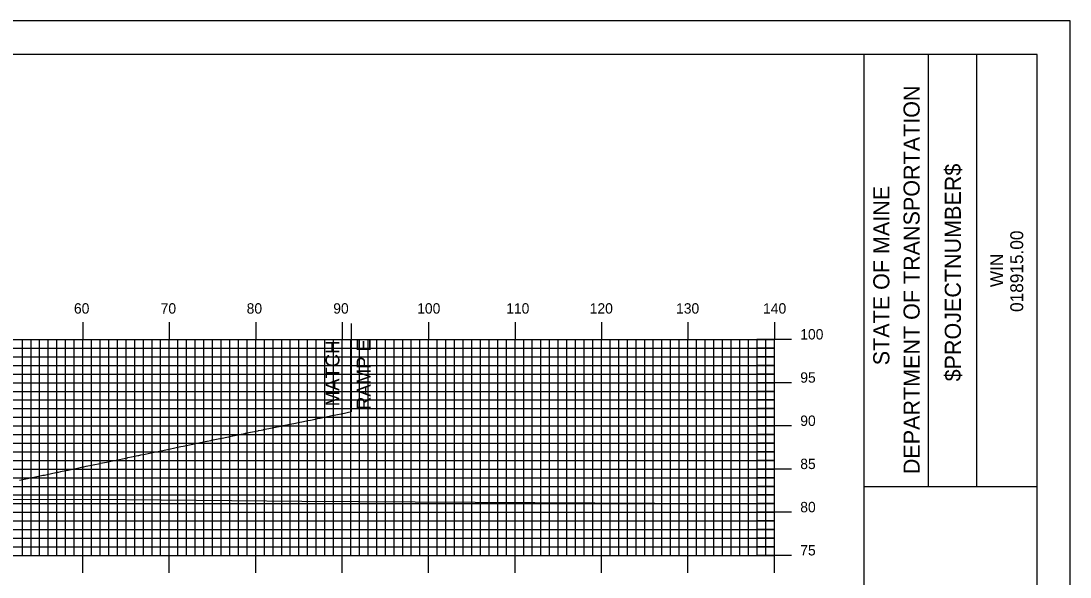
# Model space of a CAD drawing. Extents: x 1757069 to 1757412, y 442591 to 442811.
# Drawn here: x 1757287.4 to 1757408.8, y 442746.2 to 442810.5 of the extents above; entities that cross this region are included whole.
import ezdxf

# ---------------------------------------------------------------- set-up
doc = ezdxf.new("R2010")
doc.units = 0
for name, color, linetype in [('ANNOTATION', 7, 'Continuous'), ('BORDER', 7, 'Continuous'), ('D_Roadway_Centerline', 7, 'Continuous'), ('D_Roadway_SubGrade', 7, 'Continuous'), ('H_V ANNOTATION', 7, 'Continuous'), ('MAJOR', 7, 'Continuous'), ('MINOR', 7, 'Continuous'), ('PLOT BOUNDARY', 7, 'Continuous'), ('S_Roadway_Centerline', 7, 'Continuous')]:
    doc.layers.add(name, color=color, linetype=linetype)

msp = doc.modelspace()

# ---------------------------------------------------------------- linework, layer by layer
at = {"layer": 'BORDER'}
for p, q in [((1757385, 442596.67), (1757385, 442806.67)), ((1757392.45, 442756.66), (1757392.45, 442806.66)), ((1757398.04, 442756.66), (1757398.04, 442806.66)), ((1757385, 442756.65), (1757405, 442756.65))]:
    msp.add_line(p, q, dxfattribs=at)
msp.add_lwpolyline([(1757085, 442596.67), (1757405, 442596.67), (1757405, 442806.67), (1757085, 442806.67)], close=True, dxfattribs=at)
at = {"layer": 'D_Roadway_Centerline'}
msp.add_lwpolyline([(1757287.28, 442757.38), (1757289.48, 442757.84), (1757289.97, 442757.95), (1757290.08, 442757.97), (1757290.15, 442757.98), (1757291.11, 442758.18), (1757291.68, 442758.31), (1757291.74, 442758.32), (1757291.78, 442758.32), (1757292.04, 442758.38), (1757292.21, 442758.42), (1757292.89, 442758.56), (1757293.39, 442758.66), (1757293.96, 442758.78), (1757294.44, 442758.88), (1757294.73, 442758.94), (1757295, 442759), (1757295.79, 442759.16), (1757296.59, 442759.33), (1757296.61, 442759.33), (1757296.64, 442759.34), (1757297.33, 442759.48), (1757298.17, 442759.66), (1757298.44, 442759.72), (1757298.82, 442759.79), (1757299.19, 442759.87), (1757299.74, 442759.99), (1757299.77, 442759.99), (1757299.81, 442760), (1757300.24, 442760.09), (1757300.97, 442760.24), (1757301.09, 442760.26), (1757301.3, 442760.31), (1757301.81, 442760.41), (1757302.85, 442760.63), (1757302.93, 442760.65), (1757303.11, 442760.68), (1757303.46, 442760.76), (1757304.39, 442760.95), (1757304.59, 442760.99), (1757305.23, 442761.12), (1757305.38, 442761.15), (1757305.92, 442761.27), (1757306.19, 442761.32), (1757307.32, 442761.56), (1757307.34, 442761.56), (1757307.44, 442761.58), (1757307.47, 442761.59), (1757307.65, 442761.62), (1757307.84, 442761.66), (1757308.94, 442761.89), (1757308.99, 442761.9), (1757309.4, 442761.98), (1757309.5, 442762.01), (1757310.44, 442762.2), (1757310.51, 442762.21), (1757311.46, 442762.41), (1757311.47, 442762.41), (1757311.93, 442762.51), (1757311.96, 442762.51), (1757312.72, 442762.67), (1757313.33, 442762.8), (1757313.4, 442762.81), (1757313.41, 442762.81), (1757313.49, 442762.83), (1757313.58, 442762.85), (1757314.87, 442763.11), (1757314.93, 442763.12), (1757315.22, 442763.18), (1757315.45, 442763.23), (1757315.51, 442763.24), (1757315.7, 442763.28), (1757316.32, 442763.41), (1757316.68, 442763.48), (1757317.51, 442763.65), (1757317.67, 442763.69), (1757317.77, 442763.71), (1757318.57, 442763.87), (1757319.21, 442764), (1757319.35, 442764.03), (1757319.49, 442764.06), (1757320.14, 442764.19), (1757320.64, 442764.29), (1757320.94, 442764.35), (1757321.46, 442764.46), (1757321.88, 442764.55), (1757322.05, 442764.58), (1757322.19, 442764.61), (1757322.54, 442764.68), (1757323.24, 442764.82), (1757323.4, 442764.86), (1757323.41, 442764.86), (1757323.46, 442764.87), (1757323.68, 442764.91), (1757324.86, 442765.15), (1757325.32, 442765.25), (1757325.33, 442765.25), (1757325.35, 442765.25), (1757325.65, 442765.31)], dxfattribs=at)
at = {"layer": 'D_Roadway_SubGrade'}
msp.add_line((1757325.65, 442775.53), (1757325.65, 442765.31), dxfattribs=at)
at = {"layer": 'MAJOR'}
for p, q in [((1757294.6, 442775.67), (1757294.6, 442773.67)), ((1757304.6, 442775.67), (1757304.6, 442773.67)), ((1757314.6, 442775.67), (1757314.6, 442773.67)), ((1757324.6, 442775.67), (1757324.6, 442773.67)), ((1757334.6, 442775.67), (1757334.6, 442773.67)), ((1757344.6, 442775.67), (1757344.6, 442773.67)), ((1757354.6, 442775.67), (1757354.6, 442773.67)), ((1757364.6, 442775.67), (1757364.6, 442773.67)), ((1757374.6, 442775.67), (1757374.6, 442773.67)), ((1757094.6, 442773.67), (1757374.6, 442773.67)), ((1757094.6, 442773.67), (1757374.6, 442773.67)), ((1757294.6, 442748.67), (1757294.6, 442773.67)), ((1757304.6, 442748.67), (1757304.6, 442773.67)), ((1757314.6, 442748.67), (1757314.6, 442773.67)), ((1757324.6, 442748.67), (1757324.6, 442773.67)), ((1757334.6, 442748.67), (1757334.6, 442773.67)), ((1757344.6, 442748.67), (1757344.6, 442773.67)), ((1757354.6, 442748.67), (1757354.6, 442773.67)), ((1757364.6, 442748.67), (1757364.6, 442773.67)), ((1757376.6, 442773.67), (1757372.59, 442773.67)), ((1757374.6, 442748.67), (1757374.6, 442773.67)), ((1757374.6, 442748.67), (1757374.6, 442773.67)), ((1757094.6, 442768.67), (1757374.6, 442768.67)), ((1757376.6, 442768.67), (1757372.59, 442768.67)), ((1757094.6, 442763.67), (1757374.6, 442763.67)), ((1757376.6, 442763.67), (1757372.59, 442763.67)), ((1757094.6, 442758.67), (1757374.6, 442758.67)), ((1757376.6, 442758.67), (1757372.59, 442758.67)), ((1757094.6, 442753.67), (1757374.6, 442753.67)), ((1757376.6, 442753.67), (1757372.59, 442753.67)), ((1757094.6, 442748.67), (1757374.6, 442748.67)), ((1757094.6, 442748.67), (1757374.6, 442748.67)), ((1757294.6, 442746.66), (1757294.6, 442748.67)), ((1757304.6, 442746.66), (1757304.6, 442748.67)), ((1757314.6, 442746.66), (1757314.6, 442748.67)), ((1757324.6, 442746.66), (1757324.6, 442748.67)), ((1757334.6, 442746.66), (1757334.6, 442748.67)), ((1757344.6, 442746.66), (1757344.6, 442748.67)), ((1757354.6, 442746.66), (1757354.6, 442748.67)), ((1757364.6, 442746.66), (1757364.6, 442748.67)), ((1757376.6, 442748.67), (1757372.59, 442748.67)), ((1757374.6, 442746.66), (1757374.6, 442748.67))]:
    msp.add_line(p, q, dxfattribs=at)
at = {"layer": 'MINOR'}
for p, q in [((1757287.6, 442748.67), (1757287.6, 442773.67)), ((1757288.6, 442748.67), (1757288.6, 442773.67)), ((1757289.6, 442748.67), (1757289.6, 442773.67)), ((1757290.6, 442748.67), (1757290.6, 442773.67)), ((1757291.6, 442748.67), (1757291.6, 442773.67)), ((1757292.6, 442748.67), (1757292.6, 442773.67)), ((1757293.6, 442748.67), (1757293.6, 442773.67)), ((1757295.6, 442748.67), (1757295.6, 442773.67)), ((1757296.6, 442748.67), (1757296.6, 442773.67)), ((1757297.6, 442748.67), (1757297.6, 442773.67)), ((1757298.6, 442748.67), (1757298.6, 442773.67)), ((1757299.6, 442748.67), (1757299.6, 442773.67)), ((1757300.6, 442748.67), (1757300.6, 442773.67)), ((1757301.6, 442748.67), (1757301.6, 442773.67)), ((1757302.6, 442748.67), (1757302.6, 442773.67)), ((1757303.6, 442748.67), (1757303.6, 442773.67)), ((1757305.6, 442748.67), (1757305.6, 442773.67)), ((1757306.6, 442748.67), (1757306.6, 442773.67)), ((1757307.6, 442748.67), (1757307.6, 442773.67)), ((1757308.6, 442748.67), (1757308.6, 442773.67)), ((1757309.6, 442748.67), (1757309.6, 442773.67)), ((1757310.6, 442748.67), (1757310.6, 442773.67)), ((1757311.6, 442748.67), (1757311.6, 442773.67)), ((1757312.6, 442748.67), (1757312.6, 442773.67)), ((1757313.6, 442748.67), (1757313.6, 442773.67)), ((1757315.6, 442748.67), (1757315.6, 442773.67)), ((1757316.6, 442748.67), (1757316.6, 442773.67)), ((1757317.6, 442748.67), (1757317.6, 442773.67)), ((1757318.6, 442748.67), (1757318.6, 442773.67)), ((1757319.6, 442748.67), (1757319.6, 442773.67)), ((1757320.6, 442748.67), (1757320.6, 442773.67)), ((1757321.6, 442748.67), (1757321.6, 442773.67)), ((1757322.6, 442748.67), (1757322.6, 442773.67)), ((1757323.6, 442748.67), (1757323.6, 442773.67)), ((1757325.6, 442748.67), (1757325.6, 442773.67)), ((1757326.6, 442748.67), (1757326.6, 442773.67)), ((1757327.6, 442748.67), (1757327.6, 442773.67)), ((1757328.6, 442748.67), (1757328.6, 442773.67)), ((1757329.6, 442748.67), (1757329.6, 442773.67)), ((1757330.6, 442748.67), (1757330.6, 442773.67)), ((1757331.6, 442748.67), (1757331.6, 442773.67)), ((1757332.6, 442748.67), (1757332.6, 442773.67)), ((1757333.6, 442748.67), (1757333.6, 442773.67)), ((1757335.6, 442748.67), (1757335.6, 442773.67)), ((1757336.6, 442748.67), (1757336.6, 442773.67)), ((1757337.6, 442748.67), (1757337.6, 442773.67)), ((1757338.6, 442748.67), (1757338.6, 442773.67)), ((1757339.6, 442748.67), (1757339.6, 442773.67)), ((1757340.6, 442748.67), (1757340.6, 442773.67)), ((1757341.6, 442748.67), (1757341.6, 442773.67)), ((1757342.6, 442748.67), (1757342.6, 442773.67)), ((1757343.6, 442748.67), (1757343.6, 442773.67)), ((1757345.6, 442748.67), (1757345.6, 442773.67)), ((1757346.6, 442748.67), (1757346.6, 442773.67)), ((1757347.6, 442748.67), (1757347.6, 442773.67)), ((1757348.6, 442748.67), (1757348.6, 442773.67)), ((1757349.6, 442748.67), (1757349.6, 442773.67)), ((1757350.6, 442748.67), (1757350.6, 442773.67)), ((1757351.6, 442748.67), (1757351.6, 442773.67)), ((1757352.6, 442748.67), (1757352.6, 442773.67)), ((1757353.6, 442748.67), (1757353.6, 442773.67)), ((1757355.6, 442748.67), (1757355.6, 442773.67)), ((1757356.6, 442748.67), (1757356.6, 442773.67)), ((1757357.6, 442748.67), (1757357.6, 442773.67)), ((1757358.6, 442748.67), (1757358.6, 442773.67)), ((1757359.6, 442748.67), (1757359.6, 442773.67)), ((1757360.6, 442748.67), (1757360.6, 442773.67)), ((1757361.6, 442748.67), (1757361.6, 442773.67)), ((1757362.6, 442748.67), (1757362.6, 442773.67)), ((1757363.6, 442748.67), (1757363.6, 442773.67)), ((1757365.6, 442748.67), (1757365.6, 442773.67)), ((1757366.6, 442748.67), (1757366.6, 442773.67)), ((1757367.6, 442748.67), (1757367.6, 442773.67)), ((1757368.6, 442748.67), (1757368.6, 442773.67)), ((1757369.6, 442748.67), (1757369.6, 442773.67)), ((1757370.6, 442748.67), (1757370.6, 442773.67)), ((1757371.6, 442748.67), (1757371.6, 442773.67)), ((1757372.6, 442748.67), (1757372.6, 442773.67)), ((1757373.6, 442748.67), (1757373.6, 442773.67)), ((1757094.6, 442772.67), (1757374.6, 442772.67)), ((1757094.6, 442771.67), (1757374.6, 442771.67)), ((1757374.6, 442772.67), (1757372.59, 442772.67)), ((1757374.6, 442771.67), (1757372.59, 442771.67)), ((1757094.6, 442770.67), (1757374.6, 442770.67)), ((1757374.6, 442770.67), (1757372.59, 442770.67)), ((1757094.6, 442769.67), (1757374.6, 442769.67)), ((1757374.6, 442769.67), (1757372.59, 442769.67)), ((1757094.6, 442767.67), (1757374.6, 442767.67)), ((1757094.6, 442766.67), (1757374.6, 442766.67)), ((1757374.6, 442767.67), (1757372.59, 442767.67)), ((1757374.6, 442766.67), (1757372.59, 442766.67)), ((1757094.6, 442765.67), (1757374.6, 442765.67)), ((1757374.6, 442765.67), (1757372.59, 442765.67)), ((1757094.6, 442764.67), (1757374.6, 442764.67)), ((1757374.6, 442764.67), (1757372.59, 442764.67)), ((1757094.6, 442762.67), (1757374.6, 442762.67)), ((1757374.6, 442762.67), (1757372.59, 442762.67)), ((1757094.6, 442761.67), (1757374.6, 442761.67)), ((1757094.6, 442760.67), (1757374.6, 442760.67)), ((1757374.6, 442761.67), (1757372.59, 442761.67)), ((1757374.6, 442760.67), (1757372.59, 442760.67)), ((1757094.6, 442759.67), (1757374.6, 442759.67)), ((1757374.6, 442759.67), (1757372.59, 442759.67)), ((1757094.6, 442757.67), (1757374.6, 442757.67)), ((1757374.6, 442757.67), (1757372.59, 442757.67)), ((1757094.6, 442756.67), (1757374.6, 442756.67)), ((1757374.6, 442756.67), (1757372.59, 442756.67)), ((1757094.6, 442755.67), (1757374.6, 442755.67)), ((1757094.6, 442754.67), (1757374.6, 442754.67)), ((1757374.6, 442755.67), (1757372.59, 442755.67)), ((1757374.6, 442754.67), (1757372.59, 442754.67)), ((1757094.6, 442752.67), (1757374.6, 442752.67)), ((1757374.6, 442752.67), (1757372.59, 442752.67)), ((1757094.6, 442751.67), (1757374.6, 442751.67)), ((1757374.6, 442751.67), (1757372.59, 442751.67)), ((1757094.6, 442750.67), (1757374.6, 442750.67)), ((1757094.6, 442749.67), (1757374.6, 442749.67)), ((1757374.6, 442750.67), (1757372.59, 442750.67)), ((1757374.6, 442749.67), (1757372.59, 442749.67))]:
    msp.add_line(p, q, dxfattribs=at)
at = {"layer": 'PLOT BOUNDARY'}
msp.add_lwpolyline([(1757068.81, 442590.55), (1757408.81, 442590.55), (1757408.81, 442810.55), (1757068.81, 442810.55)], close=True, dxfattribs=at)
at = {"layer": 'S_Roadway_Centerline'}
msp.add_lwpolyline([(1757094.6, 442753.7), (1757106.02, 442753.69), (1757125.8, 442753.96), (1757135.34, 442753.91), (1757159.12, 442753.84), (1757182.03, 442754.12), (1757202.03, 442754.31), (1757204.09, 442754.32), (1757230.57, 442754.75), (1757249.03, 442754.84), (1757258.63, 442754.86), (1757284.4, 442755.15), (1757295.54, 442755.17), (1757319.95, 442754.95), (1757333.06, 442754.89), (1757374.6, 442754.64)], dxfattribs=at)

# ---------------------------------------------------------------- texts
at = {"layer": 'ANNOTATION'}
for s, p in [('MATCH', (1757324.28, 442765.94)), ('RAMP E', (1757327.88, 442765.51))]:
    msp.add_text(s, height=1.6, rotation=90, dxfattribs=at).set_placement(p)
at = {"layer": 'BORDER'}
for s, height, p in [('DEPARTMENT OF TRANSPORTATION', 1.8635, (1757391.41, 442758.08)), ('$PROJECTNUMBER$', 1.8635, (1757396.18, 442768.82)), ('STATE OF MAINE', 1.8635, (1757387.91, 442770.69)), ('018915.00', 1.491, (1757403.39, 442776.86)), ('WIN', 1.491, (1757401.07, 442779.73))]:
    msp.add_text(s, height=height, rotation=90, dxfattribs=at).set_placement(p)
at = {"layer": 'H_V ANNOTATION'}
for s, p in [('60', (1757293.57, 442776.67)), ('70', (1757303.6, 442776.67)), ('80', (1757313.55, 442776.67)), ('90', (1757323.57, 442776.67)), ('100', (1757333.28, 442776.67)), ('110', (1757343.58, 442776.67)), ('120', (1757353.24, 442776.67)), ('130', (1757363.23, 442776.67)), ('140', (1757373.3, 442776.67)), ('100', (1757377.6, 442773.67)), ('95', (1757377.6, 442768.67)), ('90', (1757377.6, 442763.67)), ('85', (1757377.6, 442758.67)), ('80', (1757377.6, 442753.67)), ('75', (1757377.6, 442748.67))]:
    msp.add_text(s, height=1.2, dxfattribs=at).set_placement(p)

doc.saveas('drawing.dxf')
